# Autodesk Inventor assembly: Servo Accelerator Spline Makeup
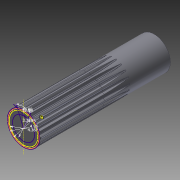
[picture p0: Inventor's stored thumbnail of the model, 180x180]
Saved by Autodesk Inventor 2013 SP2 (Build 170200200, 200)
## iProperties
Created: 2020-02
Part Number: Servo Accelerator Spline Makeup
Document SubType Name: Assembly
Designer: DELL
Author: DELL
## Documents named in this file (3)
- C:\Users\DELL\Dropbox\Inventor\Projects\Quadcopter F450\Assemblies\Servo - Design Accelerator Spline Tutorial\Archive\Servo - Design Accelerator Spline Tutorial.iam
- C:\Users\DELL\Dropbox\Inventor\Projects\Quadcopter F450\5mm Shaft - Spline Tutorial.ipt
- C:\Users\DELL\Dropbox\Inventor\Projects\Quadcopter F450\Assemblies\Servo - Design Accelerator Spline Tutorial\Design Accelerator\Involute Spline Connection2.iam
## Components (2 placed, 2 different names)
1. Shaft Test:1
2. Involute Spline Connection:1 [sub-assembly]
